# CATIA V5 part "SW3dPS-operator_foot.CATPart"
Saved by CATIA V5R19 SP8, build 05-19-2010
Part number: SW3dPS-operator_foot
Revision: ANY
Definition: SW3dPS-operator_foot
Source: Unknown
Bounding box of the stored display mesh (mm): x -46.285 to 213.36, y 0 to 127, z -47.498 to 47.498
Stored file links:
  G:\EU_thinkMotion\CFAO_2010\MMS_groupe1\MMS_groupe1\OK\rragonneau\rragonneau\SW3dPS-operator_foot.CATPart
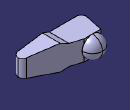
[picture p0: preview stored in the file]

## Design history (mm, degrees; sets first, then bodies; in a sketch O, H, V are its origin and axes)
Body1 "NONE" (main body)
  Solid1 "Manifold Solid #11217": solid without history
